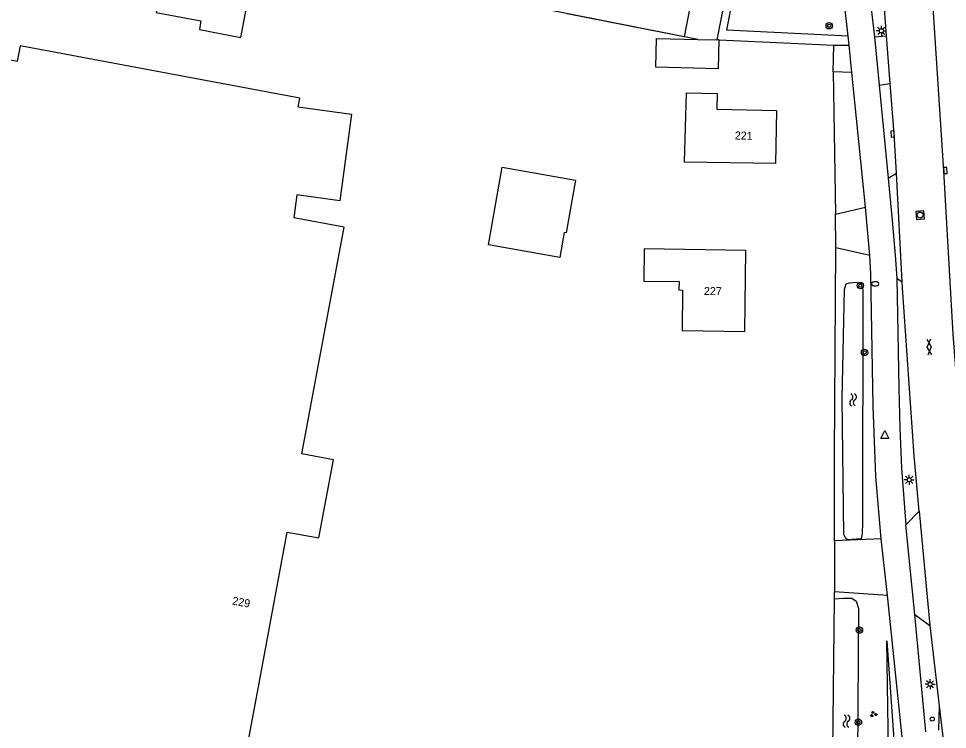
# Model space of a CAD drawing. Extents: x 132994 to 136000, y 393499 to 395512.
# Drawn here: x 133766.6 to 133882.7, y 394394.8 to 394483.5 of the extents above; entities that cross this region are included whole.
import ezdxf

# ---------------------------------------------------------------- set-up
doc = ezdxf.new("R2010")
doc.units = 0
for name, color, linetype in [('gg-afsc-hekwerk', 7, 'Continuous'), ('gg-anno-huisnummerreeks BGT', 7, 'Continuous'), ('gg-bbg-bijgebouw', 7, 'Continuous'), ('gg-bbg-gedigitaliseerde bebouwing', 7, 'Continuous'), ('gg-bbg-gedigitaliseerde bijgebouw', 7, 'Continuous'), ('gg-bbg-hoofdgebouw', 7, 'Continuous'), ('gg-knt-BGT kruinlijn', 7, 'Continuous'), ('gg-knt-bovenkant onderkant talud', 7, 'Continuous'), ('gg-knt-verharding', 7, 'Continuous'), ('gg-kntw-bovenkant insteek waterloop', 7, 'Continuous'), ('gt-afsc-standplaatsafbakening', 7, 'Continuous'), ('gt-grn-groengrens', 7, 'Continuous'), ('gt-grn-weggrens', 7, 'Continuous'), ('gt-symb-boom', 7, 'Continuous'), ('gt-symb-brandkraan', 7, 'Continuous'), ('gt-symb-gesloten verharding', 7, 'Continuous'), ('gt-symb-groenvak', 7, 'Continuous'), ('gt-symb-kolk', 7, 'Continuous'), ('gt-symb-lichtmast', 7, 'Continuous'), ('gt-symb-rioolschacht', 7, 'Continuous'), ('gt-symb-verkeersbordpaal', 7, 'Continuous'), ('gt-symb-waterafsluiter', 7, 'Continuous'), ('gt-symb-watersymbool', 7, 'Continuous')]:
    doc.layers.add(name, color=color, linetype=linetype)

# ---------------------------------------------------------------- blocks, each defined once
blk = doc.blocks.new('gt0-LMAST')
at = {"layer": 'gt-symb-lichtmast'}
for p, q in [((-0.18, 0.17), (-0.45, 0.44)), ((0, 0.25), (0, 0.62)), ((0.17, 0.17), (0.44, 0.44)), ((-0.25, 0), (-0.63, 0)), ((-0.18, -0.18), (-0.45, -0.45)), ((0, -0.25), (0, -0.63)), ((0.44, -0.45), (0.17, -0.18)), ((0.25, 0), (0.62, 0))]:
    blk.add_line(p, q, dxfattribs=at)
blk.add_circle((0, 0), 0.25, dxfattribs=at)
blk = doc.blocks.new('gt0-BOOM')
at = {"layer": 'gt-symb-boom'}
for radius in [0.4, 0.2]:
    blk.add_circle((0, 0), radius, dxfattribs=at)
blk = doc.blocks.new('gt0-KOLK')
at = {"layer": 'gt-symb-kolk'}
blk.add_lwpolyline([(0, 0), (0.37, 0), (0.37, 0.4), (-0.38, 0.4), (-0.38, 0), (0, 0)], dxfattribs=at)
blk = doc.blocks.new('gt0-RS')
at = {"layer": 'gt-symb-rioolschacht'}
blk.add_lwpolyline([(-0.5, -0.5), (0.5, -0.5), (0.5, 0.5), (-0.5, 0.5)], close=True, dxfattribs=at)
blk.add_circle((0, 0), 0.375, dxfattribs=at)
blk = doc.blocks.new('gt0-WAFSL')
at = {"layer": 'gt-symb-waterafsluiter'}
for p, q in [((-0.5, -0.33), (0, 0.67)), ((0, 0.67), (0.5, -0.33)), ((0.5, -0.33), (-0.5, -0.33))]:
    blk.add_line(p, q, dxfattribs=at)
blk = doc.blocks.new('gt0-GESVH1')
at = {"layer": 'gt-symb-gesloten verharding'}
for p, q in [((-0.99, -0.26), (0.01, 0.24)), ((0.01, -0.26), (-0.99, 0.24)), ((0.01, 0.24), (1.01, -0.26)), ((1.01, 0.24), (0.01, -0.26))]:
    blk.add_line(p, q, dxfattribs=at)
blk = doc.blocks.new('gt0-WA')
at = {"layer": 'gt-symb-watersymbool'}
for centre, start, end in [((-0.32, 0.02), 28.0725, 151.9275), ((0.43, 0.42), 208.0725, 331.9275), ((-0.32, -0.43), 28.0725, 151.9275), ((0.43, -0.03), 208.0725, 331.9275)]:
    blk.add_arc(centre, 0.425, start, end, dxfattribs=at)
blk = doc.blocks.new('gt0-BR')
at = {"layer": 'gt-symb-brandkraan'}
for centre, radius, start, end in [((-0.24, 0), 0.206, 107.5669, 252.4331), ((0.6, -2.66), 3, 106.892, 107.5669), ((0, -0.69), 0.938, 73.108, 106.892), ((-0.6, -2.66), 3, 72.4331, 73.108), ((0.24, 0), 0.206, 287.567, 72.4331), ((0.6, 2.66), 3, 252.4331, 253.108), ((0, 0.69), 0.938, 253.108, 286.8921), ((-0.6, 2.66), 3, 286.8921, 287.567)]:
    blk.add_arc(centre, radius, start, end, dxfattribs=at)
blk = doc.blocks.new('gt0-VPAAL')
at = {"layer": 'gt-symb-verkeersbordpaal'}
blk.add_circle((0, 0), 0.25, dxfattribs=at)
blk = doc.blocks.new('gt0-GRVAK')
at = {"layer": 'gt-symb-groenvak'}
for p, q in [((-0.11, 0.19), (-0.23, 0.24)), ((-0.18, 0.15), (0.09, 0.15)), ((-0.09, 0.21), (-0.16, 0.32)), ((-0.05, 0.21), (-0.05, 0.39)), ((0, 0.21), (0.06, 0.32)), ((0.01, 0.19), (0.13, 0.24)), ((0.26, -0.05), (0.2, 0.06)), ((0.3, -0.05), (0.3, 0.13)), ((0.35, -0.05), (0.41, 0.06)), ((-0.25, -0.23), (-0.36, -0.18)), ((-0.32, -0.26), (-0.05, -0.26)), ((-0.23, -0.21), (-0.29, -0.1)), ((-0.18, -0.2), (-0.18, -0.02)), ((-0.14, -0.21), (-0.07, -0.1)), ((-0.12, -0.23), (0, -0.18)), ((0.24, -0.07), (0.12, -0.02)), ((0.17, -0.11), (0.44, -0.11)), ((0.37, -0.07), (0.49, -0.02))]:
    blk.add_line(p, q, dxfattribs=at)

msp = doc.modelspace()

# ---------------------------------------------------------------- linework, layer by layer
at = {"layer": 'gg-afsc-hekwerk'}
for p, q in [((133857.51, 394500), (133853.86, 394480.88)), ((133868.55, 394418.33), (133868.54, 394429.05)), ((133868.55, 394418.33), (133868.55, 394411.96)), ((133868.54, 394411.09), (133868.55, 394411.96)), ((133868.22, 394383.61), (133868.54, 394411.09))]:
    msp.add_line(p, q, dxfattribs=at)
msp.add_lwpolyline([(133851.49, 394480.94), (133812.54, 394488.67), (133766.78, 394497.29)], dxfattribs=at)
at = {"layer": 'gg-bbg-bijgebouw'}
for p, q in [((133854.14, 394480.87), (133853.86, 394480.88)), ((133854.05, 394477.27), (133854.14, 394480.87))]:
    msp.add_line(p, q, dxfattribs=at)
msp.add_lwpolyline([(133784.89, 394489.9), (133783.82, 394484.31), (133789.41, 394483.24), (133789.21, 394482.18), (133794.38, 394481.19), (133795.65, 394487.84), (133784.89, 394489.9)], dxfattribs=at)
at = {"layer": 'gg-bbg-gedigitaliseerde bebouwing'}
for points in [[(133861.18, 394465.44), (133849.82, 394465.62), (133850.06, 394474.26)], [(133801.55, 394472.54), (133808.23, 394471.62), (133806.75, 394460.8), (133801.39, 394461.54), (133801, 394458.66)]]:
    msp.add_lwpolyline(points, dxfattribs=at)
at = {"layer": 'gg-bbg-gedigitaliseerde bijgebouw'}
msp.add_line((133851.49, 394480.94), (133853.86, 394480.88), dxfattribs=at)
for points in [[(133854.05, 394477.27), (133846.21, 394477.46), (133846.32, 394481.06), (133851.49, 394480.94)], [(133827.04, 394464.99), (133836.2, 394463.37), (133835.03, 394456.78), (133834.78, 394456.82), (133834.24, 394453.73), (133825.33, 394455.31), (133827.04, 394464.99)]]:
    msp.add_lwpolyline(points, dxfattribs=at)
at = {"layer": 'gg-bbg-hoofdgebouw'}
for points in [[(133766.81, 394480.12), (133766.45, 394478.19), (133740.48, 394483.05), (133727.52, 394413.88), (133749.15, 394409.83), (133748.48, 394406.29), (133752.41, 394405.55), (133751.83, 394402.41), (133755.76, 394401.67), (133755.17, 394398.53), (133759.1, 394397.79), (133757.92, 394391.48), (133793.71, 394384.78), (133796.67, 394400.56)], [(133801.55, 394472.54), (133801.75, 394473.59), (133766.81, 394480.12)], [(133850.06, 394474.26), (133853.89, 394474.18), (133853.85, 394472.25), (133861.32, 394472.08), (133861.18, 394465.44)], [(133802.01, 394429.21), (133807.29, 394457.48), (133801, 394458.66)], [(133844.78, 394454.78), (133844.72, 394450.77), (133849.13, 394450.71), (133849.12, 394449.66), (133849.57, 394449.65), (133849.5, 394444.59), (133857.33, 394444.47), (133857.48, 394454.59), (133844.78, 394454.78)], [(133796.67, 394400.56), (133800.2, 394419.43), (133804.13, 394418.7), (133805.96, 394428.47), (133802.01, 394429.21)]]:
    msp.add_lwpolyline(points, dxfattribs=at)
at = {"layer": 'gg-knt-BGT kruinlijn'}
msp.add_lwpolyline([(133875.08, 394405.84), (133876.44, 394386.5), (133873.79, 394378.73), (133867.54, 394375.27)], dxfattribs=at)
at = {"layer": 'gg-knt-bovenkant onderkant talud'}
msp.add_line((133875.37, 394386.54), (133875.08, 394405.84), dxfattribs=at)
at = {"layer": 'gg-knt-verharding'}
for p, q in [((133872.22, 394492.76), (133873.53, 394481.27)), ((133870.39, 394480.22), (133870.26, 394481.35)), ((133873.53, 394481.27), (133875.06, 394481.39)), ((133873.53, 394481.27), (133874.13, 394475.21)), ((133875.52, 394475.45), (133875.06, 394481.39)), ((133868.36, 394476.89), (133868.46, 394480.23)), ((133868.46, 394480.23), (133870.39, 394480.22)), ((133870.72, 394476.81), (133870.39, 394480.22)), ((133870.72, 394476.81), (133868.36, 394476.89)), ((133872.4, 394459.98), (133870.72, 394476.81)), ((133874.13, 394475.21), (133875.52, 394475.45)), ((133874.13, 394475.21), (133875.27, 394463.61)), ((133875.27, 394463.61), (133876.27, 394464.25)), ((133877.01, 394450.67), (133876.27, 394464.25)), ((133868.68, 394459.11), (133872.4, 394459.98)), ((133872.95, 394453.96), (133872.4, 394459.98)), ((133868.71, 394454.92), (133868.68, 394459.11)), ((133872.95, 394453.96), (133868.71, 394454.92)), ((133876.32, 394451.15), (133877.01, 394450.67)), ((133877.44, 394420.33), (133879.12, 394422.05)), ((133879.12, 394422.05), (133880.45, 394407.76)), ((133878.57, 394409.14), (133877.44, 394420.33)), ((133874.39, 394418.59), (133868.55, 394418.33)), ((133875.16, 394411.51), (133874.39, 394418.59)), ((133875.16, 394411.51), (133868.55, 394411.96)), ((133878.57, 394409.14), (133880.45, 394407.76)), ((133879.97, 394394.48), (133878.57, 394409.14)), ((133880.45, 394407.76), (133881.61, 394397.72)), ((133881.61, 394397.72), (133881.55, 394394.7)), ((133881.61, 394397.72), (133882.37, 394391.33))]:
    msp.add_line(p, q, dxfattribs=at)
for points in [[(133870.26, 394481.35), (133868.12, 394500.01), (133867.7, 394502.99), (133867.79, 394502.99), (133867.7, 394503.6)], [(133875.06, 394481.39), (133874.48, 394488.89), (133873.81, 394494.01)], [(133885.83, 394415.23), (133884.95, 394423.7), (133883.36, 394444.15), (133882.19, 394464.55), (133880.85, 394484.94), (133880.37, 394490.07)], [(133876.27, 394464.25), (133876.01, 394469.14), (133875.52, 394475.45)], [(133875.27, 394463.61), (133875.77, 394458.34), (133876.13, 394453.99), (133876.32, 394451.15)], [(133874.39, 394418.59), (133873.71, 394426.35), (133873.39, 394435.16), (133873.08, 394451.69), (133872.95, 394453.96)], [(133876.32, 394451.15), (133876.58, 394437.4), (133876.7, 394432.4), (133876.93, 394427.43), (133877.44, 394420.33)], [(133879.12, 394422.05), (133878.49, 394428.94), (133877.05, 394449.91), (133877.01, 394450.67)], [(133875.22, 394375.3), (133875.2, 394377.3), (133875.36, 394379.33), (133875.57, 394380.3), (133876.58, 394383.13), (133877.12, 394385.03), (133877.27, 394386.03), (133877.32, 394387.03), (133877.18, 394390.03), (133877.07, 394393.03), (133875.16, 394411.51)]]:
    msp.add_lwpolyline(points, dxfattribs=at)
at = {"layer": 'gg-kntw-bovenkant insteek waterloop'}
for points in [[(133869.96, 394418.63), (133869.7, 394419.11), (133869.49, 394436.07), (133869.8, 394449.74), (133870.02, 394450.44), (133870.41, 394450.55), (133871.25, 394450.64), (133871.89, 394450.51), (133872.08, 394449.68), (133872.06, 394420.64), (133872.02, 394419.2)], [(133872.02, 394419.2), (133871.87, 394418.58), (133870.18, 394418.48), (133869.96, 394418.63)], [(133868.54, 394411.09), (133869.66, 394411.2), (133870.7, 394411.19), (133871.26, 394410.81), (133871.54, 394409.88), (133871.41, 394391.43), (133871.13, 394386.02), (133870.85, 394384.33), (133870.31, 394382.92), (133870.09, 394382.12), (133869.57, 394381.61), (133868.94, 394381.19), (133867.58, 394380.99)]]:
    msp.add_lwpolyline(points, dxfattribs=at)
at = {"layer": 'gt-afsc-standplaatsafbakening'}
msp.add_lwpolyline([(133839.92, 394508.74), (133854.52, 394505.87), (133849.76, 394481.28), (133835.17, 394484.13)], dxfattribs=at)
at = {"layer": 'gt-grn-groengrens'}
msp.add_lwpolyline([(133870.26, 394481.35), (133855.11, 394482.1), (133859.53, 394505.11), (133858.74, 394517.92), (133857.83, 394517.84)], dxfattribs=at)
at = {"layer": 'gt-grn-weggrens'}
for p, q in [((133854.14, 394480.87), (133868.46, 394480.23)), ((133868.36, 394476.89), (133868.68, 394459.11)), ((133868.54, 394429.05), (133868.71, 394454.92))]:
    msp.add_line(p, q, dxfattribs=at)

# ---------------------------------------------------------------- block references
at = {"layer": 'gt-symb-boom'}
for p in [(133867.89, 394482.64), (133871.77, 394450.21), (133872.3, 394441.86), (133871.66, 394407.2), (133871.53, 394395.69)]:
    msp.add_blockref('gt0-BOOM', p, dxfattribs=at)
at = {"layer": 'gt-symb-brandkraan'}
msp.add_blockref('gt0-BR', (133873.63, 394450.43), dxfattribs=at)
at = {"layer": 'gt-symb-gesloten verharding', "rotation": -86.50230473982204}
msp.add_blockref('gt0-GESVH1', (133880.39, 394442.55), dxfattribs=at)
at = {"layer": 'gt-symb-groenvak'}
msp.add_blockref('gt0-GRVAK', (133873.41, 394396.7), dxfattribs=at)
at = {"layer": 'gt-symb-kolk'}
for p, rotation in [((133876.01, 394469.14), 94.41628344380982), ((133882.19, 394464.55), -86.21640974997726)]:
    msp.add_blockref('gt0-KOLK', p, dxfattribs=dict(at, rotation=rotation))
at = {"layer": 'gt-symb-lichtmast'}
for p in [(133874.4, 394482.01), (133877.88, 394425.96), (133880.49, 394400.44)]:
    msp.add_blockref('gt0-LMAST', p, dxfattribs=at)
at = {"layer": 'gt-symb-rioolschacht', "rotation": 94.47340645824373}
msp.add_blockref('gt0-RS', (133879.24, 394459.01), dxfattribs=at)
at = {"layer": 'gt-symb-verkeersbordpaal'}
msp.add_blockref('gt0-VPAAL', (133880.76, 394396.09), dxfattribs=at)
at = {"layer": 'gt-symb-waterafsluiter'}
msp.add_blockref('gt0-WAFSL', (133874.82, 394431.46), dxfattribs=at)
at = {"layer": 'gt-symb-watersymbool'}
for p, rotation in [((133870.87, 394436), -86.21640974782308), ((133870.05, 394395.88), -86.21640974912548)]:
    msp.add_blockref('gt0-WA', p, dxfattribs=dict(at, rotation=rotation))

# ---------------------------------------------------------------- texts
at = {"layer": 'gg-anno-huisnummerreeks BGT'}
for s, rotation, p in [('221', 358.8, (133856.08, 394468.45)), ('227', 359.1, (133852.23, 394449.04)), ('229', 349.4, (133793.26, 394410.4))]:
    msp.add_text(s, height=1, rotation=rotation, dxfattribs=at).set_placement(p)

doc.saveas('drawing.dxf')
